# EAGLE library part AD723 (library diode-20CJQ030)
Analog Devices AD723 2.7 V to 5.5 V RGB-to-NTSC/PAL Encoder with Load Detect and Input Termination Switch Description: The AD723 is a low cost RGB-to-NTSC/PAL encoder that converts analog red, green, and blue color component signals into their corresponding luminance and chrominance signals for display on an NTSC or PAL television. Luminance (Y) and Chrominance (C) signals are available individually for S-video, or combined for composite video (CV). All outputs are available separately and optimized for driving 75 Ohm loads. Active termination is used for lower power consumption. A smart load detect feature powers down unused outputs and can be used to monitor the continuing presence or absence of an external TV. This enables plug-and-play operation. In addition, a logic controlled triple switch at the input solves the applications problem of differing load conditions when an RGB monitor is disconnected. When an RGB monitor is not present, the R, G, and B terminations are enabled by the user. This solution ensures no loss of video bandwidth when the RGB monitor is in operation. In PC applications, flicker filter support is provided by the graphics controller, which has direct access to memory. Underscan compensation, necessary for uses other than video or DVD, is supported through choice of RGB output clocks and sync intervals. An optional luminance trap (YTRAP) provides a means of reducing cross color artifacts due to subcarrier frequency information in the Y signal. The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
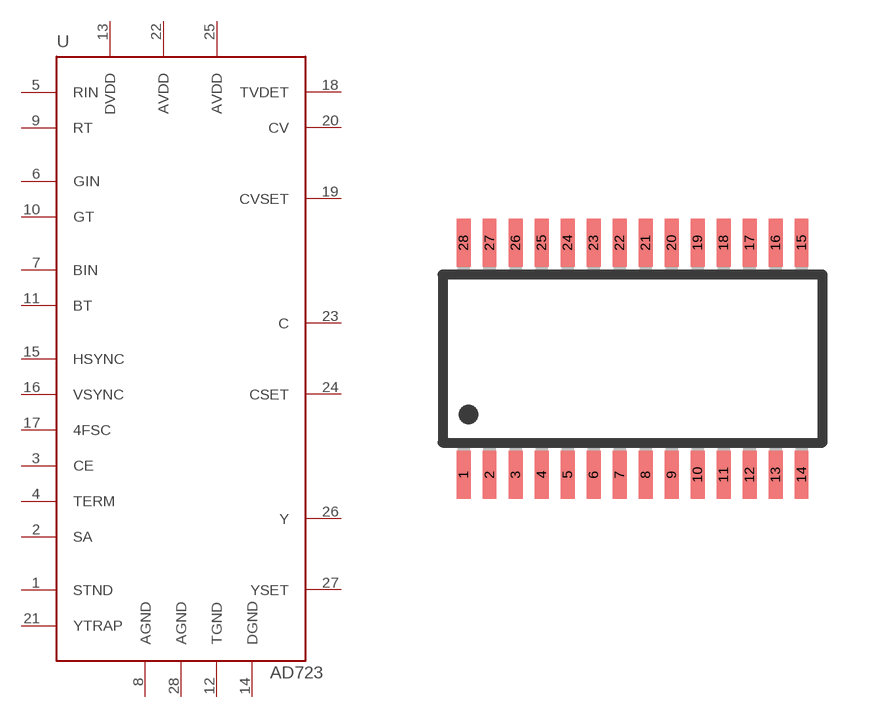
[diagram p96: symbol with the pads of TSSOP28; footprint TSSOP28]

Designator prefix U

## AD723  [TSSOP28]
1  STND  in
2  SA  in
3  CE  in
4  TERM  in
5  RIN  in
6  GIN  in
7  BIN  in
8  AGND  pwr
9  RT  in
10  GT  in
11  BT  in
12  TGND  pwr
13  DVDD  pwr
14  DGND  pwr
15  HSYNC  in
16  VSYNC  in
17  4FSC  in
18  TVDET  out
19  CVSET  out
20  CV  out
21  YTRAP  out
22  AVDD  pwr
23  C  out
24  CSET  out
25  AVDD  pwr
26  Y  out
27  YSET  out
28  AGND  pwr

## Footprint TSSOP28 (pad centres in mm)
28-Lead TSSOP Package RU-28
smd 0.35 x 1.2: 1 -4.225,-2.9; 2 -3.575,-2.9; 3 -2.925,-2.9; 4 -2.275,-2.9; 5 -1.625,-2.9; 6 -0.975,-2.9; 7 -0.325,-2.9; 8 0.325,-2.9; 9 0.975,-2.9; 10 1.625,-2.9; 11 2.275,-2.9; 12 2.925,-2.9; 13 3.575,-2.9; 14 4.225,-2.9; 15 4.225,2.9; 16 3.575,2.9; 17 2.925,2.9; 18 2.275,2.9; 19 1.625,2.9; 20 0.975,2.9; 21 0.325,2.9; 22 -0.325,2.9; 23 -0.975,2.9; 24 -1.625,2.9; 25 -2.275,2.9; 26 -2.925,2.9; 27 -3.575,2.9; 28 -4.225,2.9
